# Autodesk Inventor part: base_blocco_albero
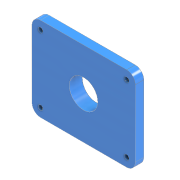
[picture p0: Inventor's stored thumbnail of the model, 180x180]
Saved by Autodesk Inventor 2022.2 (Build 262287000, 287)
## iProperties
Created: 2025-03
Part Number: base_blocco_albero
Material: Generico
Document SubType Name: Modeling
Designer: 18907419
Density: 1 g/cm^3
Appearance: Ciano
Author: 18907419
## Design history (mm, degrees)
sketch "Schizzo1"
  geometry: L1 (-40, -41)-(40, -41) reference; L2 (50, -31)-(50, 31) reference; L3 (40, 41)-(-40, 41) reference; L4 (-50, 31)-(-50, -31) reference; C1 r 2.75 at (40, -31) reference; C2 r 2.75 at (-40, 31) reference; C3 r 2.75 at (40, 31) reference; C4 r 2.75 at (-40, -31) reference; C5 r 21 at (0, 0) reference; C6 r 16.5 at (0, 0); A1 r 10 centre (-40, -31) between (-50, -31) and (-40, -41) reference; A2 r 10 centre (40, -31) between (40, -41) and (50, -31) reference; A3 r 10 centre (40, 31) between (50, 31) and (40, 41) reference; A4 r 10 centre (-40, 31) between (-40, 41) and (-50, 31) reference; 2 further points
  constraints: 1 centre point, 1 coincident
  dimensions: "d0" = 33 diameter of C6
extrude "Estrusione1" new body sketch "Schizzo1" distance "d1" = 5; taper "d2" = 0 deg
sketch "Schizzo2"
  geometry: C1 r 16.5 at (0, 0); C2 r 21 at (0, 0); 1 further point
  constraints: 2 centre point, 2 coincident
  dimensions: "d3" = 42 diameter of C2
extrude "Estrusione2" join sketch "Schizzo2" distance "d4" = 5; taper "d5" = 0 deg
node "Solido1"
node "Riferimento1"
